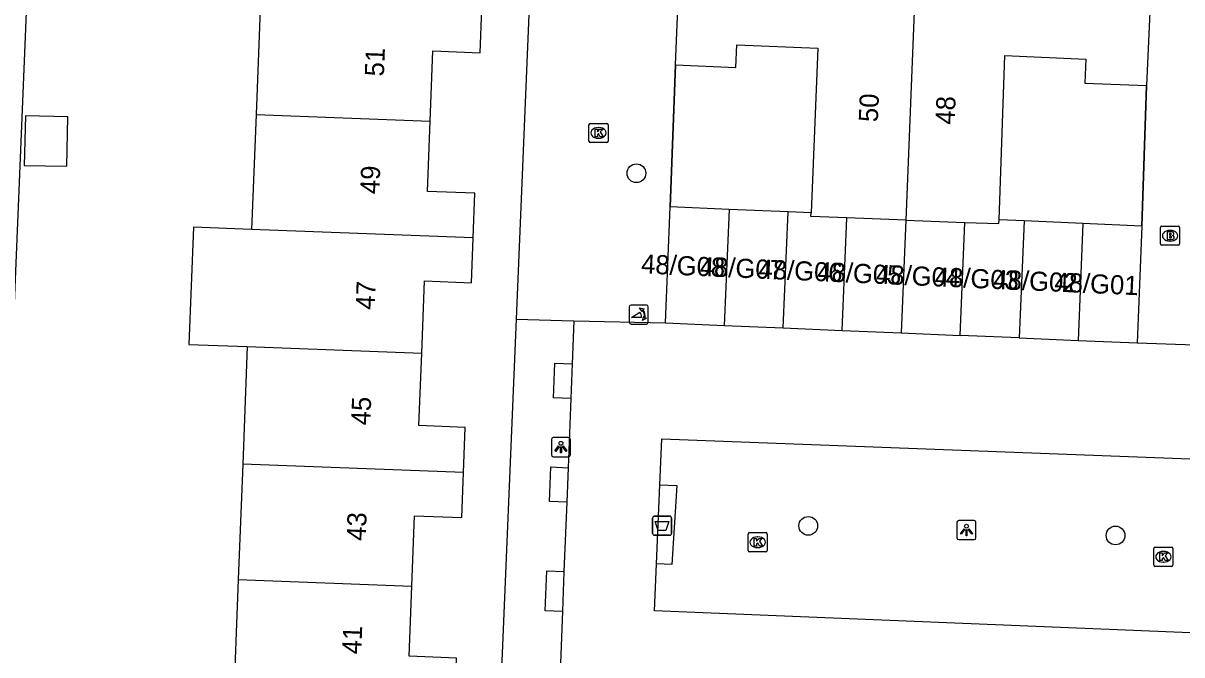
# Model space of a CAD drawing. Extents: x 160787 to 161428, y 386828 to 387483.
# Drawn here: x 161141.1 to 161201.6, y 387319.2 to 387352.2 of the extents above; entities that cross this region are included whole.
import ezdxf

# ---------------------------------------------------------------- set-up
doc = ezdxf.new("R2010")
doc.units = 0
for name, color, linetype in [('IMGEO_Afvalbak', 7, 'Continuous'), ('IMGEO_Boom', 7, 'Continuous'), ('IMGEO_Brandkraan', 7, 'Continuous'), ('IMGEO_Kolk', 7, 'Continuous'), ('IMGEO_Lichtpunt', 7, 'Continuous'), ('IMGEO_Muur', 7, 'Continuous'), ('IMGEO_Pand', 7, 'Continuous'), ('IMGEO_Pand_nummerreeks', 7, 'Continuous'), ('IMGEO_Parkeervlak_open', 7, 'Continuous'), ('IMGEO_Poller', 7, 'Continuous'), ('IMGEO_Rijbaan_lokaal_open', 7, 'Continuous'), ('IMGEO_Voetpad_open', 7, 'Continuous')]:
    doc.layers.add(name, color=color, linetype=linetype)

msp = doc.modelspace()

# ---------------------------------------------------------------- linework, layer by layer
at = {"layer": 'IMGEO_Afvalbak'}
for p, q in [((161173.942, 387325.534), (161173.942, 387326.334)), ((161173.942, 387326.334), (161173.942, 387325.534)), ((161174.042, 387326.434), (161174.832, 387326.434)), ((161174.832, 387326.434), (161174.042, 387326.434)), ((161174.932, 387326.334), (161174.932, 387325.534)), ((161174.932, 387325.534), (161174.932, 387326.334)), ((161174.832, 387325.434), (161174.042, 387325.434)), ((161174.042, 387325.434), (161174.832, 387325.434))]:
    msp.add_line(p, q, dxfattribs=at)
msp.add_lwpolyline([(161174.085, 387326.148), (161174.789, 387326.148), (161174.64, 387325.678), (161174.234, 387325.678), (161174.085, 387326.148)], dxfattribs=at)
for centre, start, end in [((161174.042, 387326.334), 90, 180), ((161174.042, 387326.334), 90, 180), ((161174.832, 387326.334), 0, 90), ((161174.832, 387326.334), 360, 90), ((161174.042, 387325.534), 180, 270), ((161174.042, 387325.534), 180, 270), ((161174.832, 387325.534), 270, 0), ((161174.832, 387325.534), 270, 0)]:
    msp.add_arc(centre, 0.1, start, end, dxfattribs=at)
at = {"layer": 'IMGEO_Boom'}
for centre in [(161173.099, 387344.343), (161182.074, 387325.927), (161198.116, 387325.427)]:
    msp.add_circle(centre, 0.489, dxfattribs=at)
at = {"layer": 'IMGEO_Brandkraan'}
for p, q in [((161200.463, 387340.654), (161200.463, 387341.506)), ((161200.538, 387341.58), (161201.39, 387341.58)), ((161201.464, 387341.506), (161201.464, 387340.654)), ((161200.974, 387340.8), (161200.949, 387340.8)), ((161200.951, 387341.36), (161200.976, 387341.36)), ((161201.39, 387340.58), (161200.538, 387340.58))]:
    msp.add_line(p, q, dxfattribs=at)
for points in [[(161200.463, 387340.654), (161200.463, 387341.506)], [(161200.538, 387341.58), (161201.39, 387341.58)], [(161201.464, 387341.506), (161201.464, 387340.654)], [(161200.811, 387341.28), (161200.811, 387340.88), (161201.024, 387340.88)], [(161201.042, 387341.28), (161200.811, 387341.28)], [(161200.99, 387341.199), (161200.936, 387341.199), (161200.936, 387341.123)], [(161200.936, 387341.123), (161200.989, 387341.123)], [(161200.998, 387341.047), (161200.936, 387341.047), (161200.936, 387340.966)], [(161200.936, 387340.966), (161200.998, 387340.966)], [(161201.39, 387340.58), (161200.538, 387340.58)]]:
    msp.add_lwpolyline(points, dxfattribs=at)
for centre, radius, start, end in [((161200.54, 387341.504), 0.0765, 91.55205, 178.44795), ((161200.54, 387341.504), 0.0765, 91.55205, 178.44795), ((161201.388, 387341.504), 0.0765, 1.55205, 88.44795), ((161201.388, 387341.504), 0.0765, 1.55205, 88.44795), ((161200.991, 387341.161), 0.0379, 267.82845, 90.93552), ((161200.999, 387341.006), 0.0404, 269.87594, 90.50774), ((161201.03, 387341.131), 0.251, 268.66757, 293.53466), ((161201.046, 387341.135), 0.145, 59.4692, 91.53667), ((161201.071, 387341.182), 0.0922, 285.51372, 58.15012), ((161201.076, 387340.99), 0.105, 301.31148, 78.98903), ((161200.54, 387340.656), 0.0765, 181.55205, 268.44795), ((161200.54, 387340.656), 0.0765, 181.55205, 268.44795), ((161201.388, 387340.656), 0.0765, 271.55205, 358.44795), ((161201.388, 387340.656), 0.0765, 271.55205, 358.44795)]:
    msp.add_arc(centre, radius, start, end, dxfattribs=at)
for centre, major_axis, ratio, start_param, end_param in [((161200.95, 387341.08), (-0.387, 0.002), 0.722429, 4.712389, 7.853982), ((161200.975, 387341.08), (-0.39, 0.002), 0.717154, 1.570796, 4.712389)]:
    msp.add_ellipse(centre, major_axis=major_axis, ratio=ratio, start_param=start_param, end_param=end_param, dxfattribs=at)
at = {"layer": 'IMGEO_Kolk'}
for p, q in [((161170.619, 387346.022), (161170.619, 387346.874)), ((161170.694, 387346.948), (161171.546, 387346.948)), ((161171.62, 387346.874), (161171.62, 387346.022)), ((161171.107, 387346.728), (161171.132, 387346.728)), ((161171.546, 387345.948), (161170.694, 387345.948)), ((161171.13, 387346.168), (161171.105, 387346.168)), ((161178.93, 387324.646), (161178.93, 387325.498)), ((161179.005, 387325.572), (161179.857, 387325.572)), ((161179.418, 387325.352), (161179.443, 387325.352)), ((161179.931, 387325.498), (161179.931, 387324.646)), ((161179.857, 387324.572), (161179.005, 387324.572)), ((161179.441, 387324.792), (161179.416, 387324.792)), ((161200.115, 387323.887), (161200.115, 387324.739)), ((161200.19, 387324.813), (161201.042, 387324.813)), ((161200.603, 387324.593), (161200.628, 387324.593)), ((161201.116, 387324.739), (161201.116, 387323.887)), ((161200.626, 387324.033), (161200.601, 387324.033)), ((161201.042, 387323.813), (161200.19, 387323.813))]:
    msp.add_line(p, q, dxfattribs=at)
for points in [[(161170.619, 387346.022), (161170.619, 387346.874)], [(161170.694, 387346.948), (161171.546, 387346.948)], [(161171.62, 387346.874), (161171.62, 387346.022)], [(161170.94, 387346.648), (161171.063, 387346.648), (161171.063, 387346.497), (161171.193, 387346.648), (161171.357, 387346.648), (161171.211, 387346.497), (161171.364, 387346.248), (161171.212, 387346.248), (161171.127, 387346.412), (161171.063, 387346.345), (161171.063, 387346.248), (161170.94, 387346.248), (161170.94, 387346.648)], [(161171.546, 387345.948), (161170.694, 387345.948)], [(161178.93, 387324.646), (161178.93, 387325.498)], [(161179.005, 387325.572), (161179.857, 387325.572)], [(161179.251, 387325.272), (161179.374, 387325.272), (161179.374, 387325.121), (161179.504, 387325.272), (161179.668, 387325.272), (161179.522, 387325.121), (161179.675, 387324.872), (161179.523, 387324.872), (161179.438, 387325.036), (161179.374, 387324.969), (161179.374, 387324.872), (161179.251, 387324.872), (161179.251, 387325.272)], [(161179.931, 387325.498), (161179.931, 387324.646)], [(161179.857, 387324.572), (161179.005, 387324.572)], [(161200.115, 387323.887), (161200.115, 387324.739)], [(161200.19, 387324.813), (161201.042, 387324.813)], [(161200.436, 387324.513), (161200.559, 387324.513), (161200.559, 387324.362), (161200.689, 387324.513), (161200.853, 387324.513), (161200.707, 387324.362), (161200.86, 387324.113), (161200.708, 387324.113), (161200.623, 387324.277), (161200.559, 387324.21), (161200.559, 387324.113), (161200.436, 387324.113), (161200.436, 387324.513)], [(161201.116, 387324.739), (161201.116, 387323.887)], [(161201.042, 387323.813), (161200.19, 387323.813)]]:
    msp.add_lwpolyline(points, dxfattribs=at)
for centre, start, end in [((161170.696, 387346.872), 91.55205, 178.44795), ((161170.696, 387346.872), 91.55205, 178.44795), ((161171.544, 387346.872), 1.55205, 88.44795), ((161171.544, 387346.872), 1.55205, 88.44795), ((161170.696, 387346.024), 181.55205, 268.44795), ((161170.696, 387346.024), 181.55205, 268.44795), ((161171.544, 387346.024), 271.55205, 358.44795), ((161171.544, 387346.024), 271.55205, 358.44795), ((161179.007, 387325.496), 91.55205, 178.44795), ((161179.007, 387325.496), 91.55205, 178.44795), ((161179.855, 387325.496), 1.55205, 88.44795), ((161179.855, 387325.496), 1.55205, 88.44795), ((161179.007, 387324.648), 181.55205, 268.44795), ((161179.007, 387324.648), 181.55205, 268.44795), ((161179.855, 387324.648), 271.55205, 358.44795), ((161179.855, 387324.648), 271.55205, 358.44795), ((161200.192, 387324.737), 91.55205, 178.44795), ((161200.192, 387324.737), 91.55205, 178.44795), ((161201.04, 387324.737), 1.55205, 88.44795), ((161201.04, 387324.737), 1.55205, 88.44795), ((161200.192, 387323.889), 181.55205, 268.44795), ((161200.192, 387323.889), 181.55205, 268.44795), ((161201.04, 387323.889), 271.55205, 358.44795), ((161201.04, 387323.889), 271.55205, 358.44795)]:
    msp.add_arc(centre, 0.0765, start, end, dxfattribs=at)
for centre, major_axis, ratio, start_param, end_param in [((161171.106, 387346.448), (-0.387, 0.002), 0.722429, 4.712389, 7.853982), ((161171.131, 387346.448), (-0.39, 0.002), 0.717154, 1.570796, 4.712389), ((161179.417, 387325.072), (-0.387, 0.002), 0.722429, 4.712389, 7.853982), ((161179.442, 387325.072), (-0.39, 0.002), 0.717154, 1.570796, 4.712389), ((161200.602, 387324.313), (-0.387, 0.002), 0.722429, 4.712389, 7.853982), ((161200.627, 387324.313), (-0.39, 0.002), 0.717154, 1.570796, 4.712389)]:
    msp.add_ellipse(centre, major_axis=major_axis, ratio=ratio, start_param=start_param, end_param=end_param, dxfattribs=at)
at = {"layer": 'IMGEO_Lichtpunt'}
for p, q in [((161169.56, 387330.535), (161168.752, 387330.535)), ((161169.56, 387330.535), (161168.752, 387330.535)), ((161168.658, 387330.44), (161168.658, 387329.633)), ((161168.658, 387330.44), (161168.658, 387329.633)), ((161169.654, 387329.633), (161169.654, 387330.44)), ((161169.654, 387329.633), (161169.654, 387330.44)), ((161168.752, 387329.539), (161169.56, 387329.539)), ((161168.752, 387329.539), (161169.56, 387329.539)), ((161189.834, 387326.112), (161189.834, 387325.305)), ((161189.834, 387326.112), (161189.834, 387325.305)), ((161190.736, 387326.207), (161189.928, 387326.207)), ((161190.736, 387326.207), (161189.928, 387326.207)), ((161190.83, 387325.305), (161190.83, 387326.112)), ((161190.83, 387325.305), (161190.83, 387326.112)), ((161189.928, 387325.211), (161190.736, 387325.211)), ((161189.928, 387325.211), (161190.736, 387325.211))]:
    msp.add_line(p, q, dxfattribs=at)
for points in [[(161169.032, 387330.104), (161169.071, 387330.076), (161168.883, 387329.814), (161168.845, 387329.841), (161169.032, 387330.104)], [(161169.134, 387330.056), (161169.181, 387330.056), (161169.181, 387329.734), (161169.134, 387329.734), (161169.134, 387330.056)], [(161169.244, 387330.076), (161169.282, 387330.103), (161169.469, 387329.841), (161169.43, 387329.813), (161169.244, 387330.076)], [(161190.208, 387325.776), (161190.247, 387325.748), (161190.059, 387325.486), (161190.021, 387325.513), (161190.208, 387325.776)], [(161190.31, 387325.728), (161190.357, 387325.728), (161190.357, 387325.406), (161190.31, 387325.406), (161190.31, 387325.728)], [(161190.42, 387325.748), (161190.458, 387325.775), (161190.645, 387325.513), (161190.606, 387325.485), (161190.42, 387325.748)]]:
    msp.add_lwpolyline(points, dxfattribs=at)
for centre in [(161169.157, 387330.238), (161190.333, 387325.91)]:
    msp.add_circle(centre, 0.0994, dxfattribs=at)
for centre, start, end in [((161168.752, 387330.44), 90, 180), ((161168.752, 387330.44), 90, 180), ((161169.56, 387330.44), 0, 90), ((161169.56, 387330.44), 0, 90), ((161168.752, 387329.633), 180, 270), ((161168.752, 387329.633), 180, 270), ((161169.56, 387329.633), 270, 0), ((161169.56, 387329.633), 270, 360), ((161189.928, 387326.112), 90, 180), ((161189.928, 387326.112), 90, 180), ((161190.736, 387326.112), 0, 90), ((161190.736, 387326.112), 0, 90), ((161189.928, 387325.305), 180, 270), ((161189.928, 387325.305), 180, 270), ((161190.736, 387325.305), 270, 0), ((161190.736, 387325.305), 270, 360)]:
    msp.add_arc(centre, 0.0946, start, end, dxfattribs=at)
at = {"layer": 'IMGEO_Muur'}
for points in [[(161175.139, 387350.002), (161174.868, 387342.585)], [(161199.497, 387341.58), (161199.737, 387348.918)]]:
    msp.add_lwpolyline(points, dxfattribs=at)
at = {"layer": 'IMGEO_Pand'}
for points in [[(161175.139, 387350.002), (161175.318, 387354.218)], [(161187.629, 387353.683), (161187.16, 387341.892)], [(161153.464, 387353.37), (161153.237, 387347.412)], [(161162.336, 387347.065), (161162.476, 387350.733), (161164.943, 387350.639), (161165.031, 387352.928)], [(161199.917, 387353.15), (161199.737, 387348.918)], [(161175.139, 387350.002), (161178.293, 387349.869), (161178.343, 387351.048), (161182.578, 387350.869), (161182.22, 387342.274)], [(161192.035, 387341.909), (161192.341, 387350.486), (161196.571, 387350.307), (161196.518, 387349.054), (161199.737, 387348.918)], [(161141.137, 387344.755), (161143.354, 387344.705), (161143.411, 387347.295), (161141.195, 387347.344), (161141.137, 387344.755)], [(161153.237, 387347.412), (161153.007, 387341.403)], [(161153.237, 387347.412), (161162.336, 387347.065)], [(161164.571, 387340.962), (161164.66, 387343.3), (161162.196, 387343.394), (161162.336, 387347.065)], [(161174.611, 387336.523), (161174.868, 387342.585)], [(161177.946, 387342.455), (161174.868, 387342.585)], [(161177.946, 387342.455), (161177.689, 387336.392)], [(161181.025, 387342.325), (161177.946, 387342.455)], [(161180.768, 387336.262), (161181.025, 387342.325)], [(161182.22, 387342.274), (161181.025, 387342.325)], [(161184.095, 387342.006), (161182.213, 387342.076), (161182.22, 387342.274)], [(161153.007, 387341.403), (161149.966, 387341.519), (161149.732, 387335.402), (161152.774, 387335.286)], [(161183.846, 387336.131), (161184.095, 387342.006)], [(161187.16, 387341.892), (161184.095, 387342.006)], [(161187.16, 387341.892), (161186.924, 387336.001)], [(161187.16, 387341.892), (161190.253, 387341.777)], [(161190.003, 387335.87), (161190.253, 387341.777)], [(161190.253, 387341.777), (161192.028, 387341.711), (161192.035, 387341.909)], [(161193.34, 387341.851), (161192.035, 387341.909)], [(161193.34, 387341.851), (161193.081, 387335.74)], [(161196.418, 387341.716), (161193.34, 387341.851)], [(161196.418, 387341.716), (161196.16, 387335.609)], [(161199.497, 387341.58), (161196.418, 387341.716)], [(161199.497, 387341.58), (161199.238, 387335.479)], [(161164.571, 387340.962), (161153.007, 387341.403)], [(161161.888, 387334.938), (161162.033, 387338.717), (161164.482, 387338.624), (161164.571, 387340.962)], [(161174.611, 387336.523), (161177.689, 387336.392)], [(161177.689, 387336.392), (161180.768, 387336.262)], [(161180.768, 387336.262), (161183.846, 387336.131)], [(161183.846, 387336.131), (161186.924, 387336.001)], [(161186.924, 387336.001), (161190.003, 387335.87)], [(161193.081, 387335.74), (161190.003, 387335.87)], [(161193.081, 387335.74), (161196.16, 387335.609)], [(161196.16, 387335.609), (161199.238, 387335.479)], [(161152.774, 387335.286), (161152.54, 387329.155)], [(161152.774, 387335.286), (161161.888, 387334.938)], [(161164.068, 387328.715), (161164.158, 387331.07), (161161.744, 387331.162), (161161.888, 387334.938)], [(161152.54, 387329.155), (161152.31, 387323.131)], [(161164.068, 387328.715), (161152.54, 387329.155)], [(161161.378, 387322.785), (161161.518, 387326.455), (161163.978, 387326.361), (161164.068, 387328.715)], [(161152.31, 387323.131), (161152.081, 387317.118)], [(161152.31, 387323.131), (161161.378, 387322.785)], [(161163.618, 387316.678), (161163.708, 387319.022), (161161.238, 387319.116), (161161.378, 387322.785)]]:
    msp.add_lwpolyline(points, dxfattribs=at)
at = {"layer": 'IMGEO_Parkeervlak_open'}
msp.add_lwpolyline([(161174.327, 387328.066), (161175.206, 387328.037), (161174.948, 387323.903), (161174.152, 387323.944)], dxfattribs=at)
at = {"layer": 'IMGEO_Poller'}
for p, q in [((161172.724, 387337.365), (161172.724, 387336.558)), ((161172.724, 387337.365), (161172.724, 387336.558)), ((161173.626, 387337.46), (161172.818, 387337.46)), ((161173.626, 387337.46), (161172.818, 387337.46)), ((161173.72, 387336.558), (161173.72, 387337.365)), ((161173.72, 387336.558), (161173.72, 387337.365)), ((161172.818, 387336.463), (161173.626, 387336.463)), ((161172.818, 387336.463), (161173.626, 387336.463))]:
    msp.add_line(p, q, dxfattribs=at)
for points in [[(161173.403, 387337.189), (161173.391, 387337.116), (161173.266, 387337.321)], [(161173.266, 387337.321), (161173.497, 387337.255), (161173.426, 387337.223)], [(161173.359, 387336.816), (161172.846, 387336.816), (161173.276, 387337.091)], [(161173.419, 387336.644), (161173.485, 387336.875), (161173.515, 387336.807)], [(161173.551, 387336.78), (161173.623, 387336.769), (161173.419, 387336.644)]]:
    msp.add_lwpolyline(points, dxfattribs=at)
for centre, radius, start, end in [((161172.818, 387337.365), 0.0946, 90, 180), ((161172.818, 387337.365), 0.0946, 90, 180), ((161173.045, 387336.876), 0.476, 351.75274, 41.16905), ((161173.045, 387336.876), 0.516, 349.35686, 42.29123), ((161173.626, 387337.365), 0.0946, 0, 90), ((161173.626, 387337.365), 0.0946, 0, 90), ((161173.031, 387336.866), 0.332, 351.32473, 42.4854), ((161172.818, 387336.558), 0.0946, 180, 270), ((161172.818, 387336.558), 0.0946, 180, 270), ((161173.626, 387336.558), 0.0946, 270, 0), ((161173.626, 387336.558), 0.0946, 270, 0)]:
    msp.add_arc(centre, radius, start, end, dxfattribs=at)
at = {"layer": 'IMGEO_Rijbaan_lokaal_open'}
for points in [[(161169.832, 387336.641), (161169.743, 387334.382)], [(161169.832, 387336.641), (161174.611, 387336.523)], [(161199.238, 387335.479), (161204.762, 387335.298)], [(161169.743, 387334.382), (161169.672, 387332.573)], [(161169.672, 387332.573), (161169.53, 387328.966)], [(161174.327, 387328.066), (161174.429, 387330.466), (161222.705, 387328.649), (161222.608, 387326.068)], [(161169.53, 387328.966), (161169.459, 387327.157)], [(161174.152, 387323.944), (161174.327, 387328.066)], [(161169.459, 387327.157), (161169.317, 387323.55)], [(161222.458, 387322.071), (161222.362, 387319.502), (161174.048, 387321.497), (161174.152, 387323.944)], [(161169.317, 387323.55), (161169.235, 387321.452)], [(161169.235, 387321.452), (161169.093, 387317.844)]]:
    msp.add_lwpolyline(points, dxfattribs=at)
at = {"layer": 'IMGEO_Voetpad_open'}
for points in [[(161139.046, 387299.512), (161142.214, 387375.996), (161142.215, 387376.018), (161142.294, 387377.909)], [(161168.496, 387376.93), (161166.813, 387336.716)], [(161174.868, 387342.585), (161175.139, 387350.002)], [(161199.737, 387348.918), (161199.497, 387341.58)], [(161166.813, 387336.716), (161165.215, 387298.514)], [(161166.813, 387336.716), (161169.832, 387336.641)], [(161169.672, 387332.573), (161168.774, 387332.609), (161168.845, 387334.418), (161169.743, 387334.382)], [(161169.459, 387327.157), (161168.561, 387327.193), (161168.632, 387329.002), (161169.53, 387328.966)], [(161169.235, 387321.452), (161168.337, 387321.488), (161168.419, 387323.586), (161169.317, 387323.55)]]:
    msp.add_lwpolyline(points, dxfattribs=at)

# ---------------------------------------------------------------- texts
at = {"layer": 'IMGEO_Pand_nummerreeks'}
for s, rotation, p in [('51', 87.75233, (161159.911, 387349.385)), ('50', 87.58108, (161185.704, 387346.999)), ('48', 87.72286, (161189.71, 387346.865)), ('49', 87.75233, (161159.67, 387343.236)), ('48/G08', 357.47481, (161173.329, 387339.116)), ('48/G07', 357.47481, (161176.394, 387338.981)), ('48/G06', 357.47481, (161179.462, 387338.846)), ('48/G05', 357.47481, (161182.53, 387338.711)), ('48/G04', 357.47481, (161185.598, 387338.575)), ('48/G03', 357.47481, (161188.666, 387338.44)), ('48/G02', 357.47481, (161191.728, 387338.305)), ('48/G01', 357.47481, (161194.913, 387338.164)), ('47', 87.75422, (161159.433, 387337.201)), ('45', 87.75233, (161159.196, 387331.165)), ('43', 87.75233, (161158.959, 387325.13)), ('41', 87.75233, (161158.726, 387319.207))]:
    msp.add_text(s, height=1, rotation=rotation, dxfattribs=at).set_placement(p)

doc.saveas('drawing.dxf')
